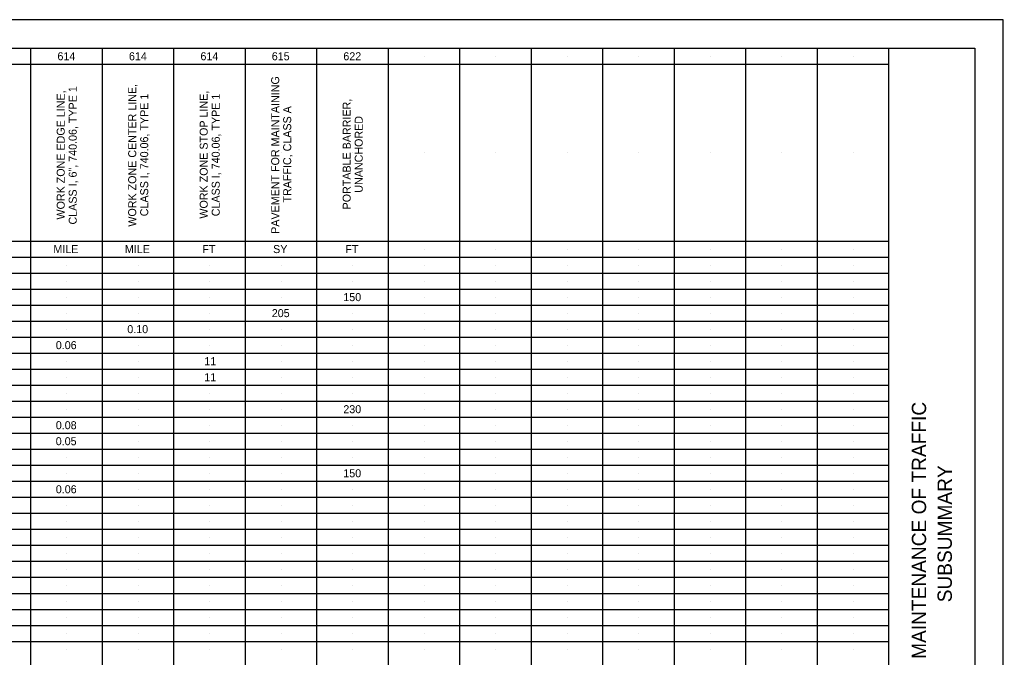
# Model space of a CAD drawing. Extents: x 0 to 66.4, y -22.2 to 22.
# Drawn here: x 16.8 to 34, y 10.85 to 22 of the extents above; entities that cross this region are included whole.
import ezdxf

# ---------------------------------------------------------------- set-up
doc = ezdxf.new("R2010")
doc.units = 0
for name, color, linetype in [('RD_P_Text', 7, 'Continuous'), ('SC_Scratch1', 7, 'Continuous'), ('SH_Border', 7, 'Continuous'), ('SH_Cut_Line', 7, 'Continuous'), ('SH_Data', 7, 'Continuous')]:
    doc.layers.add(name, color=color, linetype=linetype)

msp = doc.modelspace()

# ---------------------------------------------------------------- linework, layer by layer
at = {"layer": 'SC_Scratch1'}
for p, q in [((17.625, 21.36), (17.625, 21.36)), ((18.875, 21.36), (18.875, 21.36)), ((20.125, 21.36), (20.125, 21.36)), ((21.375, 21.36), (21.375, 21.36)), ((22.625, 21.36), (22.625, 21.36)), ((23.875, 21.36), (23.875, 21.36)), ((25.125, 21.36), (25.125, 21.36)), ((26.375, 21.36), (26.375, 21.36)), ((27.625, 21.36), (27.625, 21.36)), ((28.875, 21.36), (28.875, 21.36)), ((30.125, 21.36), (30.125, 21.36)), ((31.375, 21.36), (31.375, 21.36)), ((17.625, 19.674), (17.625, 19.674)), ((18.875, 19.674), (18.875, 19.674)), ((20.125, 19.674), (20.125, 19.674)), ((21.375, 19.674), (21.375, 19.674)), ((22.625, 19.674), (22.625, 19.674)), ((23.875, 19.674), (23.875, 19.674)), ((25.125, 19.674), (25.125, 19.674)), ((26.375, 19.674), (26.375, 19.674)), ((27.625, 19.674), (27.625, 19.674)), ((28.875, 19.674), (28.875, 19.674)), ((30.125, 19.674), (30.125, 19.674)), ((31.375, 19.674), (31.375, 19.674)), ((17.625, 17.988), (17.625, 17.988)), ((18.875, 17.988), (18.875, 17.988)), ((20.125, 17.988), (20.125, 17.988)), ((21.375, 17.988), (21.375, 17.988)), ((22.625, 17.988), (22.625, 17.988)), ((23.875, 17.988), (23.875, 17.988)), ((25.125, 17.988), (25.125, 17.988)), ((26.375, 17.988), (26.375, 17.988)), ((27.625, 17.988), (27.625, 17.988)), ((28.875, 17.988), (28.875, 17.988)), ((30.125, 17.988), (30.125, 17.988)), ((31.375, 17.988), (31.375, 17.988)), ((17.625, 17.708), (17.625, 17.708)), ((18.875, 17.708), (18.875, 17.708)), ((20.125, 17.708), (20.125, 17.708)), ((21.375, 17.708), (21.375, 17.708)), ((22.625, 17.708), (22.625, 17.708)), ((23.875, 17.708), (23.875, 17.708)), ((25.125, 17.708), (25.125, 17.708)), ((26.375, 17.708), (26.375, 17.708)), ((27.625, 17.708), (27.625, 17.708)), ((28.875, 17.708), (28.875, 17.708)), ((30.125, 17.708), (30.125, 17.708)), ((31.375, 17.708), (31.375, 17.708)), ((17.625, 17.428), (17.625, 17.428)), ((18.875, 17.428), (18.875, 17.428)), ((20.125, 17.428), (20.125, 17.428)), ((21.375, 17.428), (21.375, 17.428)), ((22.625, 17.428), (22.625, 17.428)), ((23.875, 17.428), (23.875, 17.428)), ((25.125, 17.428), (25.125, 17.428)), ((26.375, 17.428), (26.375, 17.428)), ((27.625, 17.428), (27.625, 17.428)), ((28.875, 17.428), (28.875, 17.428)), ((30.125, 17.428), (30.125, 17.428)), ((31.375, 17.428), (31.375, 17.428)), ((17.625, 17.148), (17.625, 17.148)), ((18.875, 17.148), (18.875, 17.148)), ((20.125, 17.148), (20.125, 17.148)), ((21.375, 17.148), (21.375, 17.148)), ((22.625, 17.148), (22.625, 17.148)), ((23.875, 17.148), (23.875, 17.148)), ((25.125, 17.148), (25.125, 17.148)), ((26.375, 17.148), (26.375, 17.148)), ((27.625, 17.148), (27.625, 17.148)), ((28.875, 17.148), (28.875, 17.148)), ((30.125, 17.148), (30.125, 17.148)), ((31.375, 17.148), (31.375, 17.148)), ((17.625, 16.868), (17.625, 16.868)), ((18.875, 16.868), (18.875, 16.868)), ((20.125, 16.868), (20.125, 16.868)), ((21.375, 16.868), (21.375, 16.868)), ((22.625, 16.868), (22.625, 16.868)), ((23.875, 16.868), (23.875, 16.868)), ((25.125, 16.868), (25.125, 16.868)), ((26.375, 16.868), (26.375, 16.868)), ((27.625, 16.868), (27.625, 16.868)), ((28.875, 16.868), (28.875, 16.868)), ((30.125, 16.868), (30.125, 16.868)), ((31.375, 16.868), (31.375, 16.868)), ((17.625, 16.588), (17.625, 16.588)), ((18.875, 16.588), (18.875, 16.588)), ((20.125, 16.588), (20.125, 16.588)), ((21.375, 16.588), (21.375, 16.588)), ((22.625, 16.588), (22.625, 16.588)), ((23.875, 16.588), (23.875, 16.588)), ((25.125, 16.588), (25.125, 16.588)), ((26.375, 16.588), (26.375, 16.588)), ((27.625, 16.588), (27.625, 16.588)), ((28.875, 16.588), (28.875, 16.588)), ((30.125, 16.588), (30.125, 16.588)), ((31.375, 16.588), (31.375, 16.588)), ((17.625, 16.308), (17.625, 16.308)), ((18.875, 16.308), (18.875, 16.308)), ((20.125, 16.308), (20.125, 16.308)), ((21.375, 16.308), (21.375, 16.308)), ((22.625, 16.308), (22.625, 16.308)), ((23.875, 16.308), (23.875, 16.308)), ((25.125, 16.308), (25.125, 16.308)), ((26.375, 16.308), (26.375, 16.308)), ((27.625, 16.308), (27.625, 16.308)), ((28.875, 16.308), (28.875, 16.308)), ((30.125, 16.308), (30.125, 16.308)), ((31.375, 16.308), (31.375, 16.308)), ((17.625, 16.028), (17.625, 16.028)), ((18.875, 16.028), (18.875, 16.028)), ((20.125, 16.028), (20.125, 16.028)), ((21.375, 16.028), (21.375, 16.028)), ((22.625, 16.028), (22.625, 16.028)), ((23.875, 16.028), (23.875, 16.028)), ((25.125, 16.028), (25.125, 16.028)), ((26.375, 16.028), (26.375, 16.028)), ((27.625, 16.028), (27.625, 16.028)), ((28.875, 16.028), (28.875, 16.028)), ((30.125, 16.028), (30.125, 16.028)), ((31.375, 16.028), (31.375, 16.028)), ((17.625, 15.748), (17.625, 15.748)), ((18.875, 15.748), (18.875, 15.748)), ((20.125, 15.748), (20.125, 15.748)), ((21.375, 15.748), (21.375, 15.748)), ((22.625, 15.748), (22.625, 15.748)), ((23.875, 15.748), (23.875, 15.748)), ((25.125, 15.748), (25.125, 15.748)), ((26.375, 15.748), (26.375, 15.748)), ((27.625, 15.748), (27.625, 15.748)), ((28.875, 15.748), (28.875, 15.748)), ((30.125, 15.748), (30.125, 15.748)), ((31.375, 15.748), (31.375, 15.748)), ((17.625, 15.468), (17.625, 15.468)), ((18.875, 15.468), (18.875, 15.468)), ((20.125, 15.468), (20.125, 15.468)), ((21.375, 15.468), (21.375, 15.468)), ((22.625, 15.468), (22.625, 15.468)), ((23.875, 15.468), (23.875, 15.468)), ((25.125, 15.468), (25.125, 15.468)), ((26.375, 15.468), (26.375, 15.468)), ((27.625, 15.468), (27.625, 15.468)), ((28.875, 15.468), (28.875, 15.468)), ((30.125, 15.468), (30.125, 15.468)), ((31.375, 15.468), (31.375, 15.468)), ((17.625, 15.188), (17.625, 15.188)), ((18.875, 15.188), (18.875, 15.188)), ((20.125, 15.188), (20.125, 15.188)), ((21.375, 15.188), (21.375, 15.188)), ((22.625, 15.188), (22.625, 15.188)), ((23.875, 15.188), (23.875, 15.188)), ((25.125, 15.188), (25.125, 15.188)), ((26.375, 15.188), (26.375, 15.188)), ((27.625, 15.188), (27.625, 15.188)), ((28.875, 15.188), (28.875, 15.188)), ((30.125, 15.188), (30.125, 15.188)), ((31.375, 15.188), (31.375, 15.188)), ((17.625, 14.908), (17.625, 14.908)), ((18.875, 14.908), (18.875, 14.908)), ((20.125, 14.908), (20.125, 14.908)), ((21.375, 14.908), (21.375, 14.908)), ((22.625, 14.908), (22.625, 14.908)), ((23.875, 14.908), (23.875, 14.908)), ((25.125, 14.908), (25.125, 14.908)), ((26.375, 14.908), (26.375, 14.908)), ((27.625, 14.908), (27.625, 14.908)), ((28.875, 14.908), (28.875, 14.908)), ((30.125, 14.908), (30.125, 14.908)), ((31.375, 14.908), (31.375, 14.908)), ((17.625, 14.628), (17.625, 14.628)), ((18.875, 14.628), (18.875, 14.628)), ((20.125, 14.628), (20.125, 14.628)), ((21.375, 14.628), (21.375, 14.628)), ((22.625, 14.628), (22.625, 14.628)), ((23.875, 14.628), (23.875, 14.628)), ((25.125, 14.628), (25.125, 14.628)), ((26.375, 14.628), (26.375, 14.628)), ((27.625, 14.628), (27.625, 14.628)), ((28.875, 14.628), (28.875, 14.628)), ((30.125, 14.628), (30.125, 14.628)), ((31.375, 14.628), (31.375, 14.628)), ((17.625, 14.348), (17.625, 14.348)), ((18.875, 14.348), (18.875, 14.348)), ((20.125, 14.348), (20.125, 14.348)), ((21.375, 14.348), (21.375, 14.348)), ((22.625, 14.348), (22.625, 14.348)), ((23.875, 14.348), (23.875, 14.348)), ((25.125, 14.348), (25.125, 14.348)), ((26.375, 14.348), (26.375, 14.348)), ((27.625, 14.348), (27.625, 14.348)), ((28.875, 14.348), (28.875, 14.348)), ((30.125, 14.348), (30.125, 14.348)), ((31.375, 14.348), (31.375, 14.348)), ((17.625, 14.068), (17.625, 14.068)), ((18.875, 14.068), (18.875, 14.068)), ((20.125, 14.068), (20.125, 14.068)), ((21.375, 14.068), (21.375, 14.068)), ((22.625, 14.068), (22.625, 14.068)), ((23.875, 14.068), (23.875, 14.068)), ((25.125, 14.068), (25.125, 14.068)), ((26.375, 14.068), (26.375, 14.068)), ((27.625, 14.068), (27.625, 14.068)), ((28.875, 14.068), (28.875, 14.068)), ((30.125, 14.068), (30.125, 14.068)), ((31.375, 14.068), (31.375, 14.068)), ((17.625, 13.788), (17.625, 13.788)), ((18.875, 13.788), (18.875, 13.788)), ((20.125, 13.788), (20.125, 13.788)), ((21.375, 13.788), (21.375, 13.788)), ((22.625, 13.788), (22.625, 13.788)), ((23.875, 13.788), (23.875, 13.788)), ((25.125, 13.788), (25.125, 13.788)), ((26.375, 13.788), (26.375, 13.788)), ((27.625, 13.788), (27.625, 13.788)), ((28.875, 13.788), (28.875, 13.788)), ((30.125, 13.788), (30.125, 13.788)), ((31.375, 13.788), (31.375, 13.788)), ((17.625, 13.508), (17.625, 13.508)), ((18.875, 13.508), (18.875, 13.508)), ((20.125, 13.508), (20.125, 13.508)), ((21.375, 13.508), (21.375, 13.508)), ((22.625, 13.508), (22.625, 13.508)), ((23.875, 13.508), (23.875, 13.508)), ((25.125, 13.508), (25.125, 13.508)), ((26.375, 13.508), (26.375, 13.508)), ((27.625, 13.508), (27.625, 13.508)), ((28.875, 13.508), (28.875, 13.508)), ((30.125, 13.508), (30.125, 13.508)), ((31.375, 13.508), (31.375, 13.508)), ((17.625, 13.228), (17.625, 13.228)), ((18.875, 13.228), (18.875, 13.228)), ((20.125, 13.228), (20.125, 13.228)), ((21.375, 13.228), (21.375, 13.228)), ((22.625, 13.228), (22.625, 13.228)), ((23.875, 13.228), (23.875, 13.228)), ((25.125, 13.228), (25.125, 13.228)), ((26.375, 13.228), (26.375, 13.228)), ((27.625, 13.228), (27.625, 13.228)), ((28.875, 13.228), (28.875, 13.228)), ((30.125, 13.228), (30.125, 13.228)), ((31.375, 13.228), (31.375, 13.228)), ((17.625, 12.948), (17.625, 12.948)), ((18.875, 12.948), (18.875, 12.948)), ((20.125, 12.948), (20.125, 12.948)), ((21.375, 12.948), (21.375, 12.948)), ((22.625, 12.948), (22.625, 12.948)), ((23.875, 12.948), (23.875, 12.948)), ((25.125, 12.948), (25.125, 12.948)), ((26.375, 12.948), (26.375, 12.948)), ((27.625, 12.948), (27.625, 12.948)), ((28.875, 12.948), (28.875, 12.948)), ((30.125, 12.948), (30.125, 12.948)), ((31.375, 12.948), (31.375, 12.948)), ((17.625, 12.668), (17.625, 12.668)), ((18.875, 12.668), (18.875, 12.668)), ((20.125, 12.668), (20.125, 12.668)), ((21.375, 12.668), (21.375, 12.668)), ((22.625, 12.668), (22.625, 12.668)), ((23.875, 12.668), (23.875, 12.668)), ((25.125, 12.668), (25.125, 12.668)), ((26.375, 12.668), (26.375, 12.668)), ((27.625, 12.668), (27.625, 12.668)), ((28.875, 12.668), (28.875, 12.668)), ((30.125, 12.668), (30.125, 12.668)), ((31.375, 12.668), (31.375, 12.668)), ((17.625, 12.388), (17.625, 12.388)), ((18.875, 12.388), (18.875, 12.388)), ((20.125, 12.388), (20.125, 12.388)), ((21.375, 12.388), (21.375, 12.388)), ((22.625, 12.388), (22.625, 12.388)), ((23.875, 12.388), (23.875, 12.388)), ((25.125, 12.388), (25.125, 12.388)), ((26.375, 12.388), (26.375, 12.388)), ((27.625, 12.388), (27.625, 12.388)), ((28.875, 12.388), (28.875, 12.388)), ((30.125, 12.388), (30.125, 12.388)), ((31.375, 12.388), (31.375, 12.388)), ((17.625, 12.108), (17.625, 12.108)), ((18.875, 12.108), (18.875, 12.108)), ((20.125, 12.108), (20.125, 12.108)), ((21.375, 12.108), (21.375, 12.108)), ((22.625, 12.108), (22.625, 12.108)), ((23.875, 12.108), (23.875, 12.108)), ((25.125, 12.108), (25.125, 12.108)), ((26.375, 12.108), (26.375, 12.108)), ((27.625, 12.108), (27.625, 12.108)), ((28.875, 12.108), (28.875, 12.108)), ((30.125, 12.108), (30.125, 12.108)), ((31.375, 12.108), (31.375, 12.108)), ((17.625, 11.828), (17.625, 11.828)), ((18.875, 11.828), (18.875, 11.828)), ((20.125, 11.828), (20.125, 11.828)), ((21.375, 11.828), (21.375, 11.828)), ((22.625, 11.828), (22.625, 11.828)), ((23.875, 11.828), (23.875, 11.828)), ((25.125, 11.828), (25.125, 11.828)), ((26.375, 11.828), (26.375, 11.828)), ((27.625, 11.828), (27.625, 11.828)), ((28.875, 11.828), (28.875, 11.828)), ((30.125, 11.828), (30.125, 11.828)), ((31.375, 11.828), (31.375, 11.828)), ((17.625, 11.548), (17.625, 11.548)), ((18.875, 11.548), (18.875, 11.548)), ((20.125, 11.548), (20.125, 11.548)), ((21.375, 11.548), (21.375, 11.548)), ((22.625, 11.548), (22.625, 11.548)), ((23.875, 11.548), (23.875, 11.548)), ((25.125, 11.548), (25.125, 11.548)), ((26.375, 11.548), (26.375, 11.548)), ((27.625, 11.548), (27.625, 11.548)), ((28.875, 11.548), (28.875, 11.548)), ((30.125, 11.548), (30.125, 11.548)), ((31.375, 11.548), (31.375, 11.548)), ((17.625, 11.268), (17.625, 11.268)), ((18.875, 11.268), (18.875, 11.268)), ((20.125, 11.268), (20.125, 11.268)), ((21.375, 11.268), (21.375, 11.268)), ((22.625, 11.268), (22.625, 11.268)), ((23.875, 11.268), (23.875, 11.268)), ((25.125, 11.268), (25.125, 11.268)), ((26.375, 11.268), (26.375, 11.268)), ((27.625, 11.268), (27.625, 11.268)), ((28.875, 11.268), (28.875, 11.268)), ((30.125, 11.268), (30.125, 11.268)), ((31.375, 11.268), (31.375, 11.268)), ((17.625, 10.988), (17.625, 10.988)), ((18.875, 10.988), (18.875, 10.988)), ((20.125, 10.988), (20.125, 10.988)), ((21.375, 10.988), (21.375, 10.988)), ((22.625, 10.988), (22.625, 10.988)), ((23.875, 10.988), (23.875, 10.988)), ((25.125, 10.988), (25.125, 10.988)), ((26.375, 10.988), (26.375, 10.988)), ((27.625, 10.988), (27.625, 10.988)), ((28.875, 10.988), (28.875, 10.988)), ((30.125, 10.988), (30.125, 10.988)), ((31.375, 10.988), (31.375, 10.988))]:
    msp.add_line(p, q, dxfattribs=at)
at = {"layer": 'SH_Border'}
msp.add_line((32, 0.5), (32, 21.5), dxfattribs=at)
msp.add_lwpolyline([(1.5, 21.5), (33.5, 21.5), (33.5, 0.5), (1.5, 0.5)], close=True, dxfattribs=at)
at = {"layer": 'SH_Cut_Line'}
msp.add_lwpolyline([(0, 0), (34, 0), (34, 22), (0, 22)], close=True, dxfattribs=at)
at = {"layer": 'SH_Data'}
for p, q in [((17, 0.5), (17, 21.5)), ((18.25, 0.5), (18.25, 21.5)), ((19.5, 0.5), (19.5, 21.5)), ((20.75, 0.5), (20.75, 21.5)), ((22, 0.5), (22, 21.5)), ((23.25, 0.5), (23.25, 21.5)), ((24.5, 0.5), (24.5, 21.5)), ((25.75, 0.5), (25.75, 21.5)), ((27, 0.5), (27, 21.5)), ((28.25, 0.5), (28.25, 21.5)), ((29.5, 0.5), (29.5, 21.5)), ((30.75, 0.5), (30.75, 21.5)), ((9.5, 21.22), (32, 21.22)), ((9.5, 18.128), (32, 18.128)), ((1.5, 17.848), (32, 17.848)), ((1.5, 17.568), (32, 17.568)), ((1.5, 17.288), (32, 17.288)), ((1.5, 17.008), (32, 17.008)), ((1.5, 16.728), (32, 16.728)), ((1.5, 16.448), (32, 16.448)), ((1.5, 16.168), (32, 16.168)), ((1.5, 15.888), (32, 15.888)), ((1.5, 15.608), (32, 15.608)), ((1.5, 15.328), (32, 15.328)), ((1.5, 15.048), (32, 15.048)), ((1.5, 14.768), (32, 14.768)), ((1.5, 14.488), (32, 14.488)), ((1.5, 14.208), (32, 14.208)), ((1.5, 13.928), (32, 13.928)), ((1.5, 13.648), (32, 13.648)), ((1.5, 13.368), (32, 13.368)), ((1.5, 13.088), (32, 13.088)), ((1.5, 12.808), (32, 12.808)), ((1.5, 12.528), (32, 12.528)), ((1.5, 12.248), (32, 12.248)), ((1.5, 11.968), (32, 11.968)), ((1.5, 11.688), (32, 11.688)), ((1.5, 11.408), (32, 11.408)), ((1.5, 11.128), (32, 11.128))]:
    msp.add_line(p, q, dxfattribs=at)

# ---------------------------------------------------------------- texts
at = {"layer": 'RD_P_Text'}
for s, p in [('614', (17.463, 21.29)), ('614', (18.713, 21.29)), ('614', (19.963, 21.29)), ('615', (21.21, 21.29)), ('622', (22.461, 21.29)), ('MILE', (17.392, 17.918)), ('MILE', (18.642, 17.918)), ('FT', (19.996, 17.918)), ('SY', (21.234, 17.918)), ('FT', (22.496, 17.918)), ('150', (22.461, 17.078)), ('205', (21.21, 16.798)), ('0.10', (18.684, 16.518)), ('0.06', (17.434, 16.238)), ('11', (20.031, 15.958)), ('11', (20.031, 15.678)), ('230', (22.461, 15.118)), ('0.08', (17.434, 14.838)), ('0.05', (17.433, 14.558)), ('150', (22.461, 13.998)), ('0.06', (17.434, 13.718))]:
    msp.add_text(s, height=0.14, dxfattribs=at).set_placement(p)
for s, p in [('PAVEMENT FOR MAINTAINING ', (21.34, 18.255)), ('CLASS I, 6", 740.06, TYPE 1 ', (17.8, 18.418)), ('WORK ZONE CENTER LINE, ', (18.84, 18.38)), ('WORK ZONE EDGE LINE, ', (17.59, 18.505)), ('CLASS I, 740.06, TYPE 1', (19.05, 18.562)), ('WORK ZONE STOP LINE, ', (20.09, 18.521)), ('CLASS I, 740.06, TYPE 1', (20.3, 18.562)), ('TRAFFIC, CLASS A', (21.55, 18.802)), ('PORTABLE BARRIER,', (22.59, 18.682)), ('UNANCHORED', (22.8, 18.974))]:
    msp.add_text(s, height=0.14, rotation=90, dxfattribs=at).set_placement(p)
at = {"layer": 'SH_Data'}
for s, p in [('MAINTENANCE OF TRAFFIC', (32.65, 10.822)), ('SUBSUMMARY', (33.1, 11.811))]:
    msp.add_text(s, height=0.25, rotation=90, dxfattribs=at).set_placement(p)

doc.saveas('drawing.dxf')
